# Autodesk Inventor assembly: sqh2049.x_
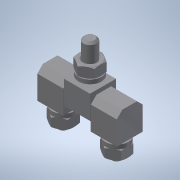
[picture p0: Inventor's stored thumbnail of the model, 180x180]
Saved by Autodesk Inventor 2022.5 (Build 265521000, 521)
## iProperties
Part Number: sqh2049.x_
Material: 一般
Document SubType Name: Assembly
Designer: ImaoCorp
Sending System: SOLIDWORKS 2017-2017317
MC: AMD64
MC_MODEL: Intel64 Family 6 Model 60 Stepping 3, GenuineIntel
OS: Windows_NT
FRU: Parasolid Version 29.0, build 201,  4-17-2017
FORMAT: text
GUISE: transmit
KEY: sqh2049
FILE: sqh2049.x_t
DATE: Wed Sep 18 16:11:06 2019
Author: ImaoCorp
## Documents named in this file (7)
- X:\14_SW2022-Inv2022\00_全2023-1023新製品(TCC)まで\s\sqh2049\SQH2049.iam
- X:\14_SW2022-Inv2022\00_全2023-1023新製品(TCC)まで\s\sqh2049\sqh2049_01.ipt
- X:\14_SW2022-Inv2022\00_全2023-1023新製品(TCC)まで\s\sqh2049\sqh2049_02.ipt
- X:\14_SW2022-Inv2022\00_全2023-1023新製品(TCC)まで\s\sqh2049\sqh2049_03.ipt
- X:\14_SW2022-Inv2022\00_全2023-1023新製品(TCC)まで\s\sqh2049\sqh2049_04.ipt
- X:\14_SW2022-Inv2022\00_全2023-1023新製品(TCC)まで\s\sqh2049\sqh2049_05.ipt
- X:\14_SW2022-Inv2022\00_全2023-1023新製品(TCC)まで\s\sqh2049\sqh2049_06.ipt
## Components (6 placed, 6 different names)
1. sqh2049_01
2. sqh2049_02
3. sqh2049_03
4. sqh2049_04
5. sqh2049_05
6. sqh2049_06
